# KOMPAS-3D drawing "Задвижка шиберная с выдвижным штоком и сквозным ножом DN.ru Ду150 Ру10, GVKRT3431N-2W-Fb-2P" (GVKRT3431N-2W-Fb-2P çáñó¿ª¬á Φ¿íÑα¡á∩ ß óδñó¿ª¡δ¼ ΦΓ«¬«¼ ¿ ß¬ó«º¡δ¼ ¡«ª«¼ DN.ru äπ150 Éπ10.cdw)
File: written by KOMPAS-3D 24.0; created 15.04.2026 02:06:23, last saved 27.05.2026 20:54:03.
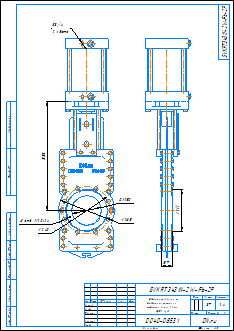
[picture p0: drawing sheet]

Document properties: Автор: DN.ru; Форматы листов документа: A3; Полное имя файла: GVKRT3431N-2W-Fb-2P Задвижка шиберная с выдвижным штоком и сквозным ножом DN.ru Ду150 Ру10.m3d; Масса: 37; Наименование: Задвижка шиберная с выдвижным штоком и сквозным ножом DN.ru Ду150 Ру10; Количество листов документа: 1; Примечание: D040-08531

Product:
- Part/product: Задвижка шиберная с выдвижным штоком и сквозным ножом DN.ru Ду150 Ру10  | designation GVKRT3431N-2W-Fb-2P
    Масса: 37
    Раздел спецификации: Прочие изделия
    Примечание: D040-08531

Views: Вид 1, Вид:1, Проекционный вид 2
Referenced files in C:\Работа\GVKRT3431N-2W-Fb-2P Задвижка шиберная со сквозным ножом DN.ru Ду100-250 Ру16\DN100\: GVKRT3431N-2W-Fb-2P Задвижка шиберная со сквозным ножом DN.ru Ду100 Ру16.m3d
Referenced files in C:\Работа\ГОТОВЫЕ ИСХОДНИКИ\GVKRT3431N-2W-Fb-2P Задвижка шиберная со сквозным ножом DN.ru Ду100-250 Ру16\DN150\: GVKRT3431N-2W-Fb-2P Задвижка шиберная с выдвижным штоком и сквозным ножом DN.ru Ду150 Ру10.m3d
Referenced files in C:\Program Files\ASCON\KOMPAS-3D v24\Templates\: Чертеж_DN.ru.cdt
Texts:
  GVKRT3431N-2W-Fb-2P
  Чертеж_DN.ru.cdt
  Задвижка шиберная с
  выдвижным штоком и
  сквозным ножом DN.ru
  Ду150 Ру10
  Задвижка шиберная с выдвижным штоком и сквозным ножом DN.ru Ду150 Ру10
  GVKRT3431N-2W-Fb-2P Задвижка шиберная с выдвижным штоком и сквозным ножом DN.ru Ду150 Ру10
Dimensions and other numbers on the sheet: 0; 3; 2; 4; 553; 240; 285; 150; 2 места; 8 отв.; 20; 57; 211; 1:4; 1; 37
